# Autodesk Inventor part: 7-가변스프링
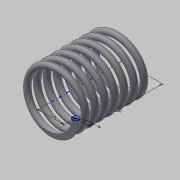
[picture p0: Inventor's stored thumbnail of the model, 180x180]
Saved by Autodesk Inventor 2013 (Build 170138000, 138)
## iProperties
Created: 2015-01
Part Number: 7-가변스프링
Material: 강철, 탄소
Document SubType Name: Modeling
Designer: Administrator
Density: 1 g/cm^3
Mass: 10.1747 g
Surface Area: 103.229 cm^2
Volume: 10.1747 cm^3
Author: Administrator
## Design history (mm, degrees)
sketch "스케치1"
  geometry: L1 (0, 0)-(17.5, 0); L2 (17.5, 0)-(17.5, 48.5); L3 (17.5, 48.5)-(0, 48.5); L4 (0, 48.5)-(0, 0); C1 r 2 at (17.5, 0)
  constraints: 8 end point, 2 parallel, 1 centre point, 1 coincident, 1 horizontal, 1 perpendicular
  dimensions: "d0" = 17.5 distance of L1.start L1.end; "d1" = 48.5 distance of L1.end L2.end (derived); "d2" = 4 diameter of C1
feature "코일1" sketch "스케치1" pitch "d3" = 10; turns "d5" = 7.5; dims "d4" = 48.5 (= d1), "d6" = 0, angle "d7" = 90 deg, angle "d8" = 90 deg, "d9" = 0, "d10" = 0
node "작업 평면1"
sketch "스케치2"
  geometry: L1 (-19.5, 0)-(-15.5, 0) reference; L2 (-19.5, 0)-(-15.5, 0) reference; 1 further point
  constraints: 2 horizontal alignment
extrude "돌출1" cut sketch "스케치2" distance "d12" = 10; taper "d13" = 0 deg
node "작업 평면2"
sketch "스케치3"
  geometry: L1 (15.5, 0)-(19.5, 0) reference; 1 further point
  constraints: 1 horizontal alignment
extrude "돌출2" cut sketch "스케치3" distance "d15" = 10; taper "d16" = 0 deg
node "솔리드1"
node "절단 모서리 투영1"
node "절단 모서리 투영2"
node "절단 모서리 투영3"
other parameters: "d11" = 0, "d14" = 48.5 (= d1)
